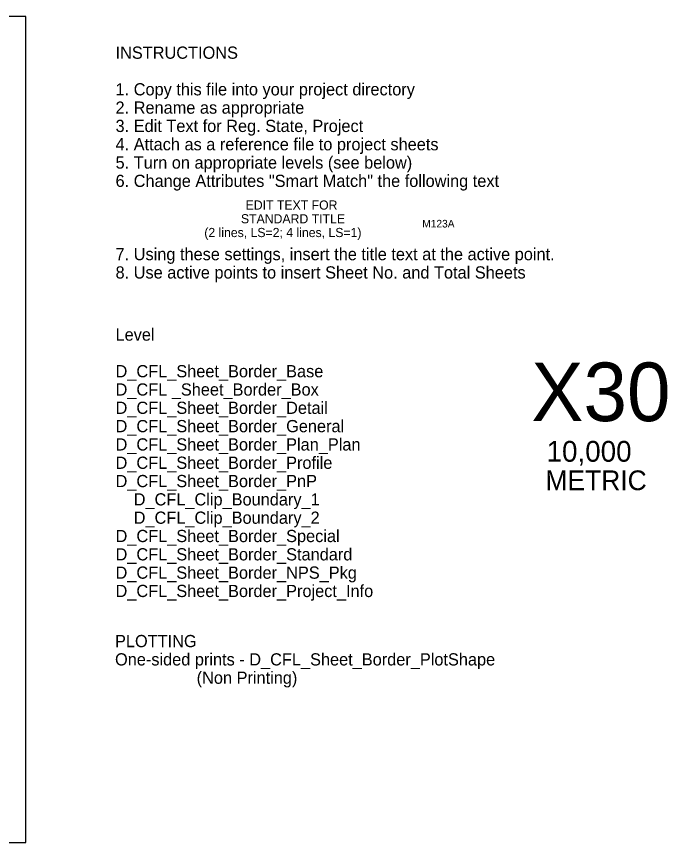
# Model space of a CAD drawing. Extents: x -27 to 606, y -3 to 268.
# Drawn here: x 392.4 to 605.7, y -2.8 to 267.8 of the extents above; entities that cross this region are included whole.
import ezdxf

# ---------------------------------------------------------------- set-up
doc = ezdxf.new("R2010")
doc.units = 0
doc.layers.add('D_CFL_Sheet_Border_ PlotShape', color=7, linetype='Continuous')
doc.layers.add('D_CFL_Sheet_Border_Base', color=7, linetype='Continuous')

msp = doc.modelspace()

# ---------------------------------------------------------------- linework, layer by layer
at = {"layer": 'D_CFL_Sheet_Border_ PlotShape'}
msp.add_line((395.49, 267.8), (395.49, 267.8), dxfattribs=at)
msp.add_lwpolyline([(-27.13, -2.8), (395.49, -2.8), (395.49, 267.8), (-27.13, 267.8)], close=True, dxfattribs=at)

# ---------------------------------------------------------------- texts
at = {"layer": 'D_CFL_Sheet_Border_Base'}
for s, height, p in [('INSTRUCTIONS', 3.9999, (424.84, 253.96)), ('1. Copy this file into your project directory', 3.9999, (424.84, 241.96)), ('2. Rename as appropriate', 3.9999, (424.84, 235.96)), ('3. Edit Text for Reg. State, Project', 3.9999, (424.84, 229.96)), ('4. Attach as a reference file to project sheets', 3.9999, (424.84, 223.96)), ('5. Turn on appropriate levels (see below)', 3.9999, (424.84, 217.96)), ('6. Change Attributes "Smart Match" the following text', 3.9999, (424.84, 211.96)), ('       EDIT TEXT FOR      ', 3, (459.67, 204.54)), ('       STANDARD TITLE     ', 3, (458.13, 200.04)), ('M123A', 2.5, (525.34, 198.68)), ('(2 lines, LS=2; 4 lines, LS=1)', 3, (453.92, 195.54)), ('7. Using these settings, insert the title text at the active point.', 3.9999, (424.84, 187.96)), ('8. Use active points to insert Sheet No. and Total Sheets', 3.9999, (424.84, 181.96)), ('Level ', 4, (424.84, 161.6)), ('X30', 19.19, (561.06, 135.24)), ('D_CFL_Sheet_Border_Base', 3.9999, (424.84, 149.6)), ('D_CFL _Sheet_Border_Box', 3.9999, (424.84, 143.61)), ('D_CFL_Sheet_Border_Detail', 3.9999, (424.84, 137.61)), ('D_CFL_Sheet_Border_General', 3.9999, (424.84, 131.61)), ('D_CFL_Sheet_Border_Plan_Plan', 3.9999, (424.84, 125.61)), ('10,000', 6.809, (566.1, 121.94)), ('D_CFL_Sheet_Border_Profile', 3.9999, (424.84, 119.61)), ('METRIC', 6.47, (565.74, 112.62)), ('D_CFL_Sheet_Border_PnP', 3.9999, (424.84, 113.61)), ('    D_CFL_Clip_Boundary_1', 3.9999, (424.84, 107.61)), ('    D_CFL_Clip_Boundary_2', 3.9999, (424.84, 101.61)), ('D_CFL_Sheet_Border_Special', 3.9999, (424.84, 95.61)), ('D_CFL_Sheet_Border_Standard', 3.9999, (424.84, 89.61)), ('D_CFL_Sheet_Border_NPS_Pkg', 3.9999, (424.84, 83.61)), ('D_CFL_Sheet_Border_Project_Info', 3.9999, (424.84, 77.61)), ('PLOTTING', 4, (424.67, 61.19)), ('One-sided prints - D_CFL_Sheet_Border_PlotShape ', 3.9999, (424.67, 55.19)), ('                  (Non Printing)', 3.9999, (424.67, 49.19))]:
    msp.add_text(s, height=height, dxfattribs=at).set_placement(p)

doc.saveas('drawing.dxf')
